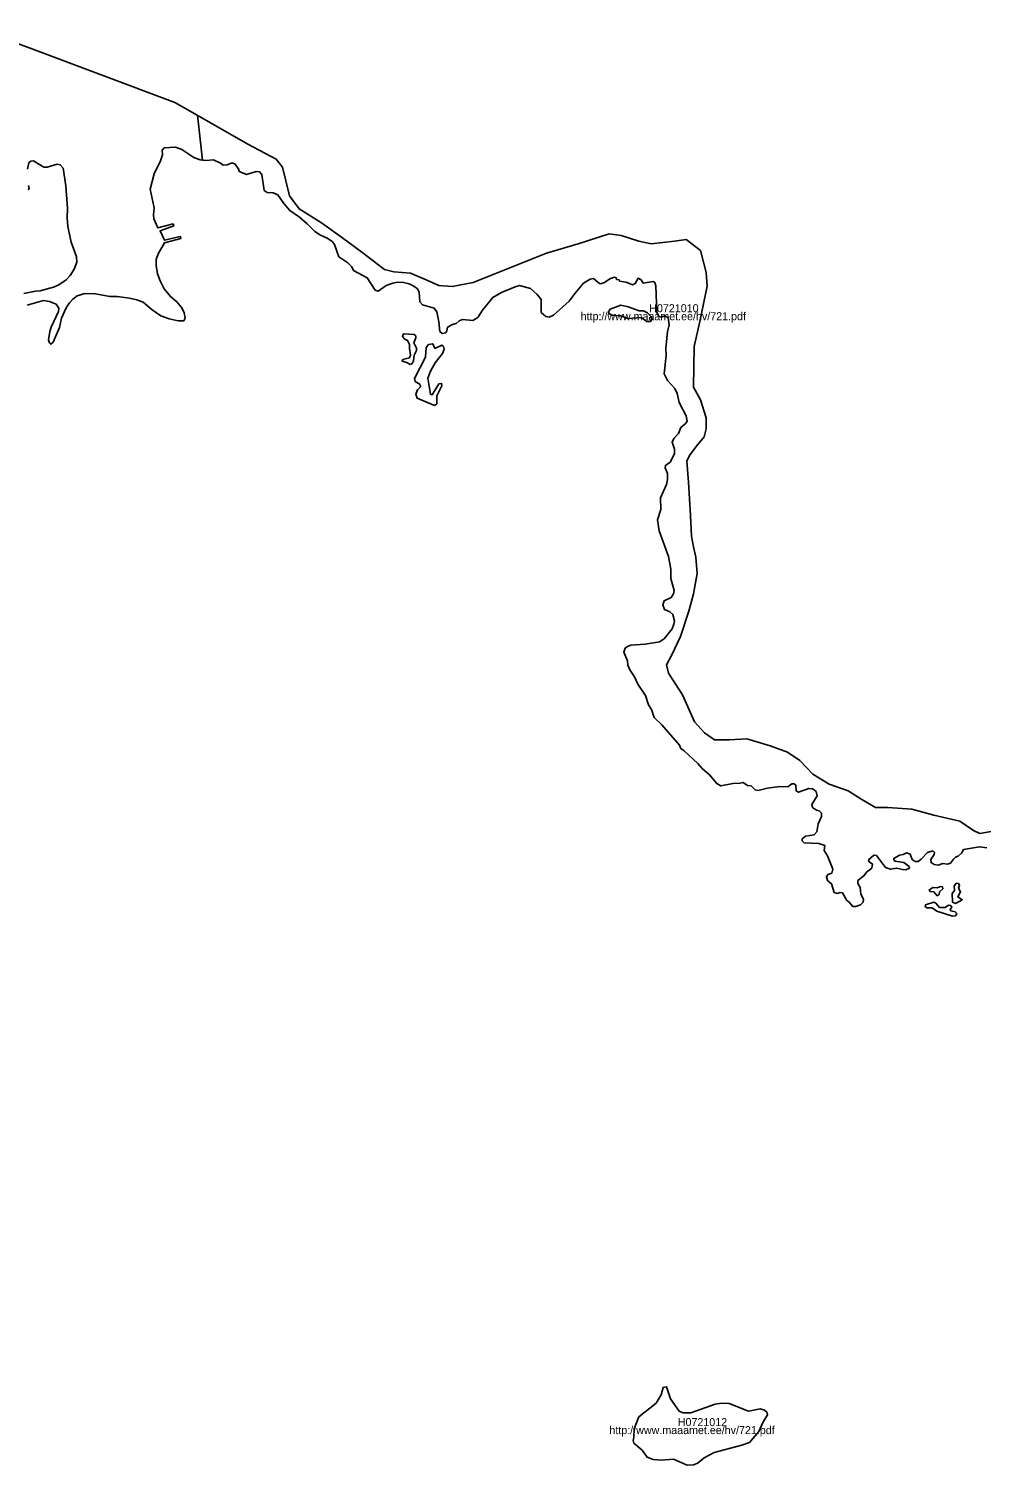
# Model space of a CAD drawing. Extents: x 369010 to 739155, y 6377141 to 6634081.
# Drawn here: x 388897 to 391875, y 6445707 to 6450195 of the extents above; entities that cross this region are included whole.
import ezdxf

# ---------------------------------------------------------------- set-up
doc = ezdxf.new("R2010")
doc.units = 0
for name, color, linetype in [('H_LINK', 7, 'Continuous'), ('H_PIIR', 7, 'Continuous'), ('H_TUNNUS', 7, 'Continuous')]:
    doc.layers.add(name, color=color, linetype=linetype)

msp = doc.modelspace()

# ---------------------------------------------------------------- linework, layer by layer
at = {"layer": 'H_PIIR'}
for points in [[(388735.84, 6450195.38), (388901.94, 6450134.86), (389354.0899, 6449965.0101), (389424.27, 6449925.6499), (389424.2814, 6449925.5534), (389440.8693, 6449784.8262), (389432.91, 6449785.9746), (389413.0401, 6449793.3246), (389375.4799, 6449818.0947), (389356.4299, 6449825.7246), (389320.7701, 6449823.5446), (389314.78, 6449815.6447), (389315.87, 6449801.7647), (389309.0599, 6449782.1647), (389289.74, 6449741.8747), (389277.22, 6449693.6846), (389289.19, 6449635.4446), (389287.02, 6449615.2946), (389288.65, 6449601.1347), (389300.35, 6449573.1046), (389348.53, 6449585.3547), (389350.44, 6449579.3646), (389307.9699, 6449564.3846), (389321.3101, 6449534.7147), (389371.12, 6449546.1447), (389372.75, 6449540.4347), (389321.3101, 6449526.0047), (389301.44, 6449491.7046), (389295.18, 6449474.8246), (389295.18, 6449455.2246), (389300.08, 6449429.9046), (389307.7, 6449407.8547), (389321.04, 6449382.5446), (389340.09, 6449358.5846), (389359.9601, 6449341.9747), (389375.74, 6449323.4747), (389383.6301, 6449307.4147), (389385.8099, 6449291.3446), (389382.27, 6449283.1847), (389364.85, 6449282.9046), (389335.7301, 6449289.1746), (389309.87, 6449298.4246), (389282.6501, 6449316.9346), (389254.62, 6449341.1646), (389235.56, 6449348.7847), (389211.88, 6449353.6846), (389174.0499, 6449358.3146), (389151.19, 6449359.1346), (389105.4599, 6449367.0246), (389072.5299, 6449367.8447), (389048.8499, 6449360.4947), (389034.69, 6449350.6947), (389024.6199, 6449338.9947), (389014.55, 6449323.4847), (389000.13, 6449291.0847), (388993.32, 6449262.2347), (388973.73, 6449216.4946), (388966.11, 6449209.4146), (388962.02, 6449213.7747), (388959.0301, 6449223.5746), (388962.84, 6449249.7047), (388967.6101, 6449263.0547), (388990.7401, 6449311.7846), (388991.56, 6449322.4047), (388982.5799, 6449335.1946), (388961.8901, 6449342.8246), (388943.3801, 6449346.0847), (388891.9399, 6449331.6547)], [(391946.6401, 6447693.9099), (391870.82, 6447680.95), (391850.47, 6447690.2), (391807.94, 6447719.8099), (391726.58, 6447738.3099), (391658.1501, 6447756.8199), (391582.78, 6447762.1101), (391543.7099, 6447762.1101), (391501.38, 6447786.55), (391459.0601, 6447814.24), (391398.83, 6447835.4101), (391348.36, 6447866.3599), (391307.67, 6447908.7101), (391268.6001, 6447934.77), (391214.8799, 6447954.32), (391141.6199, 6447977.12), (391087.8999, 6447973.8701), (391040.6901, 6447973.8701), (391009.76, 6447995.0399), (390978.8299, 6448029.2501), (390941.3899, 6448113.9499), (390897.44, 6448182.0699), (390890.93, 6448208.1301), (390907.21, 6448239.0799), (390934.88, 6448296.09), (390960.93, 6448375.8999), (390975.5801, 6448429.6501), (390986.9699, 6448493.1801), (390982.09, 6448544.3399), (390975.5801, 6448576.92), (390969.0599, 6448609.5), (390965.81, 6448674.65), (390959.2999, 6448778.9), (390954.41, 6448844.05), (390962.55, 6448861.97), (390983.72, 6448889.66), (391008.13, 6448920.6099), (391014.6499, 6448945.06), (391014.6499, 6448979.26), (390996.7399, 6449036.27), (390975.5801, 6449075.37), (390977.1999, 6449202.42), (390995.1101, 6449280.5999), (391017.9, 6449391.3699), (391014.6499, 6449433.72), (390996.7399, 6449502.1299), (390952.79, 6449536.3301), (390916.32, 6449531.45), (390843.07, 6449523.3), (390803.9999, 6449531.45), (390748.6499, 6449549.37), (390711.2099, 6449554.2501), (390615.16, 6449523.3), (390515.86, 6449493.98), (390286.33, 6449402.77), (390221.21, 6449389.7401), (390178.89, 6449392.99), (390139.82, 6449410.91), (390090.9801, 6449432.09), (390038.89, 6449435.3401), (390009.5899, 6449443.49), (389942.84, 6449493.98), (389874.47, 6449544.48), (389812.61, 6449588.46), (389742.61, 6449632.44), (389712.4299, 6449673.6901), (389690.99, 6449763.15), (389670.9099, 6449788.11), (389581.94, 6449834.5499), (389424.27, 6449925.6499), (389354.0899, 6449965.0101), (388901.94, 6450134.86), (388735.84, 6450195.38)], [(391892.3801, 6447635.5246), (391869.06, 6447639.5746), (391818.84, 6447630.7647), (391812.6599, 6447619.5747), (391802.66, 6447609.8147), (391794.0999, 6447606.7246), (391787.67, 6447600.7747), (391778.1501, 6447588.1546), (391769.59, 6447584.5847), (391753.1699, 6447586.9646), (391741.27, 6447582.2047), (391727.46, 6447583.6346), (391718.18, 6447589.8246), (391716.9901, 6447599.3446), (391727.7, 6447614.8146), (391728.89, 6447621.7146), (391723.8901, 6447626.2346), (391706.5201, 6447621.9547), (391687.25, 6447600.7747), (391677.49, 6447593.6247), (391667.73, 6447593.3946), (391659.1599, 6447599.3446), (391652.5, 6447616.0046), (391641.55, 6447620.2847), (391630.8499, 6447615.5246), (391619.4201, 6447613.1446), (391601.34, 6447602.9147), (391601.1, 6447597.6747), (391605.15, 6447594.1046), (391632.27, 6447590.2947), (391648.9301, 6447577.4446), (391650.12, 6447572.6846), (391639.29, 6447567.4446), (391628.82, 6447568.1646), (391610.02, 6447572.9247), (391591.2201, 6447569.3546), (391575.0401, 6447574.3546), (391546.96, 6447611.7147), (391539.34, 6447613.1446), (391522.69, 6447598.8647), (391524.35, 6447592.4346), (391535.3, 6447585.2946), (391532.68, 6447572.9247), (391515.78, 6447559.5947), (391509.1199, 6447549.1246), (391489.37, 6447533.6547), (391488.65, 6447524.1346), (391496.75, 6447511.9946), (391498.1699, 6447490.8146), (391506.9801, 6447475.5846), (391505.55, 6447466.3047), (391497.22, 6447458.4446), (391482.23, 6447452.4947), (391472.9501, 6447452.9747), (391460.57, 6447467.4947), (391454.15, 6447471.7746), (391440.82, 6447495.1047), (391434.1599, 6447496.0546), (391424.16, 6447493.4347), (391414.6501, 6447496.2947), (391406.5501, 6447523.6646), (391394.18, 6447533.6547), (391390.61, 6447545.3147), (391395.6101, 6447552.6947), (391407.51, 6447556.9846), (391411.31, 6447569.1146), (391393.6999, 6447610.7646), (391383.7, 6447627.6647), (391386.08, 6447643.1346), (391367.05, 6447649.7947), (391321.5899, 6447652.1746), (391315.4101, 6447657.8947), (391315.17, 6447664.5546), (391325.4, 6447672.6446), (391352.05, 6447676.9347), (391360.62, 6447685.7346), (391364.8999, 6447710.9647), (391375.3701, 6447734.2846), (391374.9, 6447744.7646), (391368, 6447751.6746), (391359.43, 6447753.8146), (391347.5299, 6447761.9046), (391345.63, 6447771.4247), (391361.81, 6447798.3146), (391358.4799, 6447811.6446), (391348.2401, 6447819.9747), (391336.1101, 6447821.6447), (391303.51, 6447809.5047), (391296.61, 6447813.7846), (391294.7, 6447832.1147), (391289.7, 6447836.3946), (391282.3299, 6447836.4046), (391270.1999, 6447827.1246), (391245.4499, 6447828.0747), (391206.66, 6447822.1247), (391177.63, 6447815.4546), (391167.6301, 6447817.1247), (391155.73, 6447829.5046), (391144.5401, 6447831.1646), (391130.27, 6447840.2147), (391120.75, 6447837.5946), (391098.62, 6447837.1147), (391061.02, 6447829.2647), (391047.93, 6447836.6447), (391025.33, 6447864.4846), (391002.72, 6447883.5246), (390989.16, 6447899.4747), (390946.5599, 6447939.2247), (390935.98, 6447946.3647), (390931.93, 6447956.5947), (390876.01, 6448020.3846), (390852.6901, 6448042.7546), (390844.12, 6448068.2146), (390834.5999, 6448082.7346), (390825.32, 6448111.5346), (390801.05, 6448147.4646), (390791.29, 6448170.0747), (390776.06, 6448191.7346), (390769.87, 6448206.7346), (390768.68, 6448220.2947), (390757.9701, 6448247.6646), (390762.0201, 6448259.8046), (390769.3999, 6448265.5146), (390779.8699, 6448269.0846), (390824.13, 6448272.1847), (390869.3501, 6448279.7947), (390883.39, 6448289.5547), (390908.6201, 6448320.7247), (390913.62, 6448334.5347), (390915.9899, 6448345.7146), (390910.7599, 6448365.4746), (390900.9999, 6448373.0846), (390884.58, 6448380.7047), (390879.1099, 6448394.9846), (390883.87, 6448408.0746), (390905.7701, 6448418.3147), (390913.1399, 6448429.5046), (390914.3301, 6448439.9746), (390904.5801, 6448477.5747), (390904.5801, 6448506.8546), (390897.2, 6448546.6046), (390867.6901, 6448626.0946), (390862.9299, 6448660.3746), (390873.64, 6448692.7446), (390871.7301, 6448729.3946), (390891.2501, 6448771.5146), (390893.6401, 6448786.5046), (390894.3, 6448805.9947), (390886.6601, 6448822.8546), (390887.7199, 6448830.7547), (390902.1999, 6448841.5546), (390915.63, 6448867.3646), (390915.63, 6448881.3146), (390908.78, 6448903.4447), (390913.7901, 6448915.0247), (390928.01, 6448930.3046), (390935.91, 6448949.2646), (390948.55, 6448959.5447), (390955.9301, 6448968.4946), (390951.98, 6448985.8747), (390930.91, 6449027.4947), (390924.33, 6449055.1447), (390916.95, 6449071.4747), (390894.0399, 6449095.9646), (390884.03, 6449117.2946), (390890.0901, 6449173.9246), (390889.0401, 6449197.6247), (390893.5099, 6449248.1946), (390899.4001, 6449270.3046), (390896.5101, 6449292.4347), (390885.18, 6449298.4846), (390875.7001, 6449293.7446), (390867.0101, 6449296.6446), (390860.96, 6449309.5446), (390857.54, 6449392.5046), (390854.64, 6449401.9847), (390849.37, 6449405.1446), (390818.3, 6449400.6746), (390811.7201, 6449410.4246), (390802.77, 6449415.6846), (390793.29, 6449398.8346), (390784.34, 6449395.4146), (390764.8499, 6449403.0447), (390743.79, 6449406.9946), (390742.4701, 6449410.9446), (390734.57, 6449411.7347), (390733.7801, 6449417.2646), (390728.5099, 6449419.3747), (390715.8701, 6449415.1647), (390694.81, 6449401.2046), (390683.4899, 6449398.5747), (390676.37, 6449403.5746), (390662.6799, 6449414.6347), (390651.8901, 6449413.3146), (390631.35, 6449399.8846), (390605.0199, 6449369.0747), (390586.85, 6449344.3147), (390538.1301, 6449300.8646), (390523.6499, 6449294.2846), (390513.64, 6449296.1246), (390499.16, 6449308.7646), (390499.16, 6449349.8546), (390486.7901, 6449365.3946), (390465.72, 6449383.5647), (390431.75, 6449393.3147), (390418.0599, 6449389.0946), (390374.8801, 6449370.9247), (390347.49, 6449355.6546), (390316.16, 6449315.8846), (390301.14, 6449293.5047), (390285.08, 6449283.7547), (390253.2201, 6449287.1847), (390242.42, 6449282.4447), (390233.21, 6449274.2746), (390222.15, 6449270.8546), (390206.3499, 6449262.4247), (390204.51, 6449251.8947), (390200.5599, 6449245.0447), (390190.02, 6449242.9346), (390182.1199, 6449249.7847), (390178.97, 6449280.0746), (390173.17, 6449310.8847), (390165, 6449322.4747), (390127.8799, 6449332.7447), (390120.24, 6449341.9647), (390118.1301, 6449371.9847), (390112.3401, 6449382.2547), (390100.7599, 6449391.2046), (390086.2699, 6449398.3146), (390069.1601, 6449402.7946), (390051.52, 6449403.0547), (390035.18, 6449400.4246), (390014.9101, 6449393.3147), (389989.1, 6449375.1446), (389980.41, 6449378.5746), (389955.4001, 6449417.2846), (389912.7401, 6449440.4546), (389906.9501, 6449451.5147), (389894.8301, 6449463.9146), (389866.66, 6449483.1446), (389853.2299, 6449521.0646), (389846.12, 6449530.5447), (389832.17, 6449540.0246), (389809.5201, 6449550.0346), (389791.88, 6449562.1446), (389767.3901, 6449585.8546), (389743.43, 6449606.6546), (389713.1501, 6449627.1946), (389694.72, 6449648.7946), (389676.29, 6449675.9146), (389661.28, 6449683.0247), (389642.0599, 6449683.5547), (389632.8299, 6449690.1246), (389625.72, 6449739.6347), (389618.8799, 6449747.7946), (389608.6099, 6449749.3747), (389578.0601, 6449739.6347), (389560.02, 6449746.7846), (389554.03, 6449750.5947), (389553.49, 6449755.7647), (389542.8701, 6449772.6446), (389533.34, 6449775.9147), (389517.29, 6449769.6447), (389505.3099, 6449768.5646), (389496.5999, 6449775.3647), (389474.8301, 6449785.4346), (389451.6901, 6449783.2647), (389440.8693, 6449784.8262), (389424.2814, 6449925.5534), (389424.27, 6449925.6499), (389581.94, 6449834.5499), (389670.9099, 6449788.11), (389690.99, 6449763.15), (389712.4299, 6449673.6901), (389742.61, 6449632.44), (389812.61, 6449588.46), (389874.47, 6449544.48), (389942.84, 6449493.98), (390009.5899, 6449443.49), (390038.89, 6449435.3401), (390090.9801, 6449432.09), (390139.82, 6449410.91), (390178.89, 6449392.99), (390221.21, 6449389.7401), (390286.33, 6449402.77), (390515.86, 6449493.98), (390615.16, 6449523.3), (390711.2099, 6449554.2501), (390748.6499, 6449549.37), (390803.9999, 6449531.45), (390843.07, 6449523.3), (390916.32, 6449531.45), (390952.79, 6449536.3301), (390996.7399, 6449502.1299), (391014.6499, 6449433.72), (391017.9, 6449391.3699), (390995.1101, 6449280.5999), (390977.1999, 6449202.42), (390975.5801, 6449075.37), (390996.7399, 6449036.27), (391014.6499, 6448979.26), (391014.6499, 6448945.06), (391008.13, 6448920.6099), (390983.72, 6448889.66), (390962.55, 6448861.97), (390954.41, 6448844.05), (390959.2999, 6448778.9), (390965.81, 6448674.65), (390969.0599, 6448609.5), (390975.5801, 6448576.92), (390982.09, 6448544.3399), (390986.9699, 6448493.1801), (390975.5801, 6448429.6501), (390960.93, 6448375.8999), (390934.88, 6448296.09), (390907.21, 6448239.0799), (390890.93, 6448208.1301), (390897.44, 6448182.0699), (390941.3899, 6448113.9499), (390978.8299, 6448029.2501), (391009.76, 6447995.0399), (391040.6901, 6447973.8701), (391087.8999, 6447973.8701), (391141.6199, 6447977.12), (391214.8799, 6447954.32), (391268.6001, 6447934.77), (391307.67, 6447908.7101), (391348.36, 6447866.3599), (391398.83, 6447835.4101), (391459.0601, 6447814.24), (391501.38, 6447786.55), (391543.7099, 6447762.1101), (391582.78, 6447762.1101), (391658.1501, 6447756.8199), (391726.58, 6447738.3099), (391807.94, 6447719.8099), (391850.47, 6447690.2), (391870.82, 6447680.95), (391946.6401, 6447693.9099)], [(388881.74, 6449367.8647), (388918.21, 6449374.9447), (388932.9099, 6449376.0347), (388974.82, 6449387.7246), (388991.1499, 6449395.3546), (389013.7501, 6449410.3246), (389027.0801, 6449424.4847), (389038.79, 6449444.6247), (389047.2201, 6449466.1347), (389046.6801, 6449482.1947), (389030.08, 6449528.7446), (389019.88, 6449577.7446), (389017.1599, 6449604.6946), (389018.79, 6449634.3746), (389013.36, 6449704.8747), (389004.65, 6449759.8646), (388995.67, 6449770.4846), (388985.87, 6449772.3947), (388955.11, 6449762.3146), (388943.9501, 6449762.5947), (388911.84, 6449782.4746), (388904.2101, 6449781.9246), (388897.95, 6449776.4847), (388893.6, 6449756.0646)], [(388896.5899, 6449705.1646), (388899.0401, 6449696.1747), (388895.78, 6449691.8246)]]:
    msp.add_lwpolyline(points, dxfattribs=at)
for points in [[(390840.3494, 6449280.3736), (390829.4261, 6449280.8702), (390812.0482, 6449292.621), (390771.1687, 6449289.8073), (390746.6741, 6449298.2481), (390724.9932, 6449299.0756), (390712.0838, 6449304.2063), (390709.4358, 6449311.323), (390715.2284, 6449319.1017), (390748.1637, 6449331.3489), (390771.4998, 6449326.3838), (390805.2625, 6449313.971), (390818.5029, 6449313.8055), (390831.7432, 6449307.6818), (390841.6735, 6449296.5931), (390845.149, 6449286.3318)], [(390089.2923, 6449145.9845), (390079.5276, 6449152.2736), (390064.3012, 6449156.2457), (390066.9493, 6449161.8728), (390087.9682, 6449167.169), (390090.9473, 6449175.7752), (390086.9752, 6449196.1322), (390087.9682, 6449208.3794), (390081.6791, 6449221.1232), (390072.4108, 6449225.2608), (390065.2941, 6449234.1981), (390068.6044, 6449242.4732), (390102.0361, 6449239.4943), (390106.8357, 6449235.5222), (390107.3323, 6449229.233), (390101.2086, 6449214.0066), (390109.6493, 6449197.2907), (390109.4839, 6449190.3395), (390101.8706, 6449175.2786), (390099.8845, 6449157.9007), (390095.9124, 6449149.7911)], [(390165.4242, 6449018.0499), (390110.9732, 6449041.3859), (390107.1668, 6449053.3022), (390112.9594, 6449066.708), (390121.7311, 6449076.1417), (390120.407, 6449083.2584), (390105.3461, 6449093.0232), (390102.6981, 6449102.6224), (390137.7849, 6449169.6515), (390139.771, 6449199.2768), (390147.0532, 6449208.7104), (390159.9626, 6449210.862), (390167.0792, 6449196.6286), (390188.0981, 6449206.8899), (390193.7252, 6449202.0903), (390196.3734, 6449194.1461), (390191.0772, 6449181.0712), (390167.9068, 6449151.777), (390152.8459, 6449125.1309), (390145.0672, 6449103.2845), (390152.6803, 6449053.3022), (390158.6385, 6449051.9782), (390179.3264, 6449085.7409), (390187.6017, 6449087.2305), (390188.5947, 6449079.9483), (390172.5409, 6449048.0062), (390173.3684, 6449023.5114)], [(391747.1459, 6447515.6046), (391753.9314, 6447513.9496), (391754.428, 6447507.4949), (391744.6633, 6447498.2267), (391743.3393, 6447490.6134), (391737.0501, 6447486.3104), (391726.4577, 6447498.3921), (391714.5415, 6447499.3851), (391711.8935, 6447503.8538), (391722.9822, 6447511.9634), (391736.5535, 6447511.467)], [(391796.3005, 6447525.8658), (391803.7483, 6447524.5417), (391806.8928, 6447519.5767), (391803.7483, 6447509.812), (391810.2029, 6447498.2267), (391801.4312, 6447483.0004), (391815.168, 6447473.8976), (391794.1489, 6447462.3122), (391784.7152, 6447466.6154), (391784.0533, 6447493.2616), (391790.8389, 6447503.1917), (391790.0113, 6447516.2666)], [(391785.2117, 6447422.0948), (391735.726, 6447438.1488), (391721.8238, 6447448.2444), (391705.1077, 6447448.2444), (391699.8117, 6447452.2165), (391700.3081, 6447457.5126), (391726.4577, 6447466.2843), (391732.7469, 6447463.1397), (391744.4977, 6447449.5685), (391761.5447, 6447449.2375), (391772.7989, 6447456.5197), (391778.9226, 6447456.3542), (391782.5637, 6447451.058), (391777.5985, 6447443.6104), (391779.2535, 6447439.4727), (391793.487, 6447436.3281), (391797.9555, 6447430.3701), (391793.818, 6447423.2534)], [(390955.0438, 6445706.8115), (390913.0057, 6445726.3408), (390874.1123, 6445722.5344), (390849.1211, 6445725.1824), (390830.0882, 6445731.637), (390814.3653, 6445753.8145), (390789.2087, 6445776.3231), (390786.3952, 6445784.5982), (390789.2087, 6445793.5356), (390789.7053, 6445821.0091), (390804.2695, 6445857.751), (390858.0583, 6445901.1131), (390873.9468, 6445926.6006), (390880.236, 6445949.9368), (390891.1591, 6445951.5918), (390903.4065, 6445914.85), (390930.0526, 6445876.2876), (390942.2998, 6445870.8259), (390967.291, 6445870.4948), (391042.7608, 6445897.9685), (391062.6213, 6445901.1131), (391086.9504, 6445900.1201), (391146.6974, 6445875.9564), (391183.6048, 6445882.9076), (391197.0106, 6445878.6046), (391205.2857, 6445871.6534), (391206.4443, 6445864.5368), (391191.549, 6445840.2076), (391179.3016, 6445812.0719), (391150.1729, 6445778.1436), (391126.6713, 6445769.2064), (391039.7817, 6445746.5324), (391008.6671, 6445729.651), (390989.9651, 6445713.9281), (390976.3938, 6445708.4665)]]:
    msp.add_lwpolyline(points, close=True, dxfattribs=at)

# ---------------------------------------------------------------- texts
at = {"layer": 'H_LINK'}
for p in [(390622.5484, 6449284.6026), (390712.3805, 6445804.2016)]:
    msp.add_text('http://www.maaamet.ee/hv/721.pdf', height=25, rotation=0, dxfattribs=at).set_placement(p)
at = {"layer": 'H_TUNNUS'}
for s, p in [('H0721010', (390836.9024, 6449309.6026)), ('H0721012', (390926.1088, 6445829.2016))]:
    msp.add_text(s, height=25, rotation=0, dxfattribs=at).set_placement(p)

doc.saveas('drawing.dxf')
